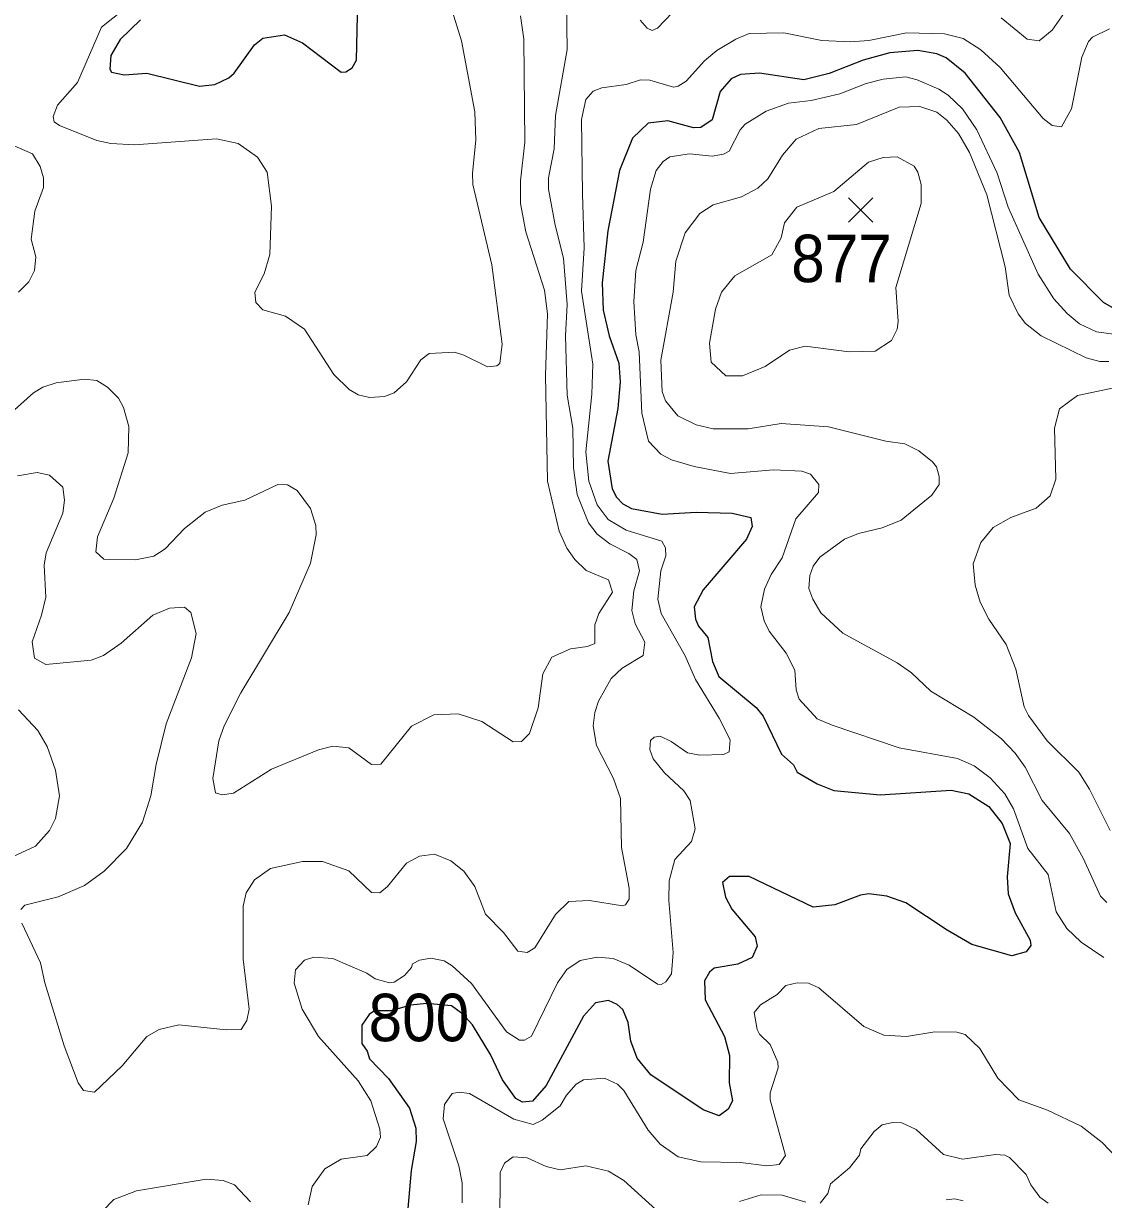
# Model space of a CAD drawing. Extents: x 265 to 291.4, y 7731.5 to 7759.6.
# Drawn here: x 281.619 to 283.439, y 7750.728 to 7752.709 of the extents above; entities that cross this region are included whole.
import ezdxf
from ezdxf.enums import TextEntityAlignment as Align

# ---------------------------------------------------------------- set-up
doc = ezdxf.new("R2010")
doc.units = 0
doc.header["$LTSCALE"] = 0.032
for name, color, linetype, lineweight in [('1', 7, 'Continuous', 25), ('2', 7, 'Continuous', 13), ('21', 7, 'Continuous', 25), ('61', 7, 'Continuous', 13)]:
    doc.layers.add(name, color=color, linetype=linetype, lineweight=lineweight)

msp = doc.modelspace()

# ---------------------------------------------------------------- linework, layer by layer
at = {"layer": '1'}
for points in [[(281.8164, 7752.7151), (281.7822, 7752.6817), (281.7663, 7752.6546), (281.7647, 7752.6316), (281.7671, 7752.6268), (281.7886, 7752.622), (281.8268, 7752.6252), (281.9159, 7752.6029), (281.9413, 7752.6061), (281.9652, 7752.6172), (281.9739, 7752.6252), (282.0081, 7752.6729), (282.0225, 7752.6841), (282.059, 7752.6896), (282.0893, 7752.6761), (282.1545, 7752.6268), (282.1625, 7752.6276), (282.1728, 7752.6339), (282.18, 7752.6467), (282.1823, 7752.7477)], [(283.4615, 7752.2258), (283.4392, 7752.2386), (283.3835, 7752.2951), (283.331, 7752.3818), (283.2976, 7752.4916), (283.265, 7752.5504), (283.2061, 7752.6252), (283.1743, 7752.6507), (283.1584, 7752.6578), (283.1266, 7752.6634), (283.0789, 7752.6594), (283.0343, 7752.6467), (282.9771, 7752.6244), (282.9341, 7752.614), (282.8593, 7752.6252), (282.8275, 7752.6228), (282.8116, 7752.6156), (282.7933, 7752.5942), (282.7797, 7752.5465), (282.7607, 7752.5337), (282.748, 7752.5329), (282.705, 7752.5448), (282.6716, 7752.5409), (282.6453, 7752.5154), (282.6238, 7752.4613), (282.6039, 7752.3595), (282.5944, 7752.272), (282.596, 7752.2259), (282.6063, 7752.1829), (282.6222, 7752.1368), (282.6246, 7752.105)], [(282.6246, 7752.105), (282.6206, 7752.0604), (282.6039, 7751.9713), (282.6111, 7751.9252), (282.6183, 7751.9109), (282.6294, 7751.8997), (282.6437, 7751.8917)], [(282.6437, 7751.8917), (282.6955, 7751.8822), (282.7527, 7751.8854), (282.8132, 7751.8838), (282.845, 7751.8766), (282.8474, 7751.8615), (282.8378, 7751.8401), (282.7646, 7751.755), (282.7495, 7751.7263), (282.7519, 7751.7056), (282.7567, 7751.6937), (282.7726, 7751.6746), (282.7805, 7751.634), (282.7909, 7751.6086), (282.8537, 7751.5568), (282.8657, 7751.5418), (282.8967, 7751.4781), (282.9166, 7751.4598), (282.923, 7751.4479), (282.9564, 7751.428), (282.985, 7751.4168), (283.063, 7751.4097), (283.1823, 7751.4176), (283.2125, 7751.4113), (283.2459, 7751.3898), (283.2682, 7751.3612), (283.2817, 7751.3278), (283.2769, 7751.2713), (283.2785, 7751.2427), (283.2904, 7751.2108), (283.3159, 7751.1647), (283.3167, 7751.1559), (283.3087, 7751.1448), (283.2849, 7751.1384), (283.2173, 7751.1575), (283.1759, 7751.1814), (283.1059, 7751.2275), (283.0741, 7751.2387), (283.0439, 7751.2426), (283.0296, 7751.2403), (282.9866, 7751.2243), (282.95, 7751.2204), (282.8418, 7751.2721), (282.8092, 7751.2721), (282.7973, 7751.2617), (282.802, 7751.2371), (282.8131, 7751.2172), (282.8521, 7751.1703), (282.8553, 7751.1544), (282.8474, 7751.1353), (282.8227, 7751.1241), (282.7829, 7751.1177), (282.775, 7751.1106), (282.767, 7751.0963), (282.7678, 7751.0645), (282.8004, 7751.0024), (282.8092, 7750.9706), (282.8084, 7750.9245), (282.814, 7750.8942), (282.8068, 7750.8799), (282.7917, 7750.8688), (282.7647, 7750.8791), (282.6764, 7750.9379), (282.6533, 7750.9658), (282.6429, 7750.9945), (282.6382, 7751.0263), (282.6294, 7751.0478), (282.6198, 7751.0565), (282.6048, 7751.0629), (282.5833, 7751.0589), (282.5626, 7751.0366), (282.4997, 7750.9197), (282.4767, 7750.8934), (282.46, 7750.8918), (282.4488, 7750.8982), (282.4266, 7750.9292), (282.4059, 7750.9722), (282.3757, 7751.0223), (282.3595, 7751.0402), (282.3402, 7751.0542), (282.299, 7751.0582), (282.2711, 7751.0555), (282.2386, 7751.0456), (282.2107, 7751.0456), (282.2014, 7751.0396), (282.1895, 7751.0215), (282.1895, 7750.9905), (282.1983, 7750.9777), (282.2022, 7750.965), (282.234, 7750.9316), (282.2698, 7750.8815), (282.2802, 7750.8481), (282.281, 7750.8258), (282.2722, 7750.7765), (282.2667, 7750.7129)]]:
    msp.add_lwpolyline(points, dxfattribs=at)
at = {"layer": '2'}
for points in [[(281.8268, 7752.7636), (281.7504, 7752.7024), (281.7098, 7752.6093), (281.6764, 7752.5711), (281.6693, 7752.552), (281.6708, 7752.5433), (281.6796, 7752.5369), (281.7425, 7752.5114), (281.7663, 7752.5067), (281.8061, 7752.5043), (281.9445, 7752.5146), (281.9811, 7752.5067), (282.0137, 7752.4836), (282.0296, 7752.4582), (282.0368, 7752.4009), (282.0344, 7752.3197), (282.0248, 7752.2871), (282.0089, 7752.2561), (282.0105, 7752.2386), (282.0225, 7752.2267), (282.0607, 7752.2155), (282.0925, 7752.194), (282.1418, 7752.1177), (282.168, 7752.0922), (282.1832, 7752.0835), (282.2023, 7752.0787), (282.2277, 7752.0803), (282.2436, 7752.0867), (282.2643, 7752.105), (282.2889, 7752.1423), (282.3025, 7752.1527), (282.3454, 7752.1551), (282.3613, 7752.1503), (282.4011, 7752.1304), (282.417, 7752.132), (282.4218, 7752.136), (282.4258, 7752.1686), (282.4083, 7752.3022), (282.3764, 7752.4375), (282.3756, 7752.4566), (282.3812, 7752.5123), (282.3796, 7752.56), (282.3574, 7752.6793), (282.3335, 7752.7557)], [(282.5729, 7751.2315), (282.6286, 7751.2228), (282.6334, 7751.2244), (282.6398, 7751.2339), (282.6398, 7751.2522), (282.627, 7751.3206), (282.6254, 7751.4033), (282.6135, 7751.4368), (282.5849, 7751.4924), (282.5793, 7751.5259), (282.5817, 7751.5481), (282.588, 7751.5672), (282.6095, 7751.6054), (282.6278, 7751.6229), (282.6636, 7751.6444), (282.666, 7751.6666), (282.6501, 7751.6977), (282.6445, 7751.72), (282.6477, 7751.7534), (282.6573, 7751.7868), (282.6525, 7751.8059), (282.639, 7751.8162), (282.6071, 7751.8321), (282.5857, 7751.8488), (282.5713, 7751.8679), (282.5523, 7751.9156), (282.5459, 7751.9602), (282.5451, 7752.027), (282.5355, 7752.0827), (282.5324, 7752.1829), (282.5355, 7752.2354), (282.5292, 7752.3134), (282.5149, 7752.3691), (282.5037, 7752.4295), (282.5037, 7752.4486), (282.5133, 7752.4979), (282.5157, 7752.5536), (282.5355, 7752.665), (282.534, 7752.7429)], [(283.2666, 7752.7183), (283.3104, 7752.6825), (283.331, 7752.6793), (283.3525, 7752.6976), (283.3923, 7752.7541)], [(282.4568, 7752.7215), (282.4624, 7752.6825), (282.464, 7752.5091), (282.4568, 7752.4438), (282.4568, 7752.4057), (282.4655, 7752.3579), (282.4974, 7752.2593)], [(282.6581, 7752.7143), (282.67, 7752.7008), (282.6787, 7752.6968), (282.6875, 7752.7008), (282.7129, 7752.727)], [(283.4496, 7752.7), (283.4209, 7752.6857), (283.4138, 7752.6785), (283.4026, 7752.6523), (283.3851, 7752.5648), (283.3684, 7752.5345), (283.3525, 7752.5369), (283.3374, 7752.5488), (283.265, 7752.6348), (283.2324, 7752.6642), (283.203, 7752.6833), (283.1712, 7752.6912), (283.1075, 7752.6928), (283.0439, 7752.6801), (283.0121, 7752.6777), (282.9643, 7752.6801), (282.9007, 7752.6928), (282.8418, 7752.692), (282.8195, 7752.6825), (282.7877, 7752.6634), (282.767, 7752.6459), (282.736, 7752.6117), (282.7225, 7752.6029), (282.7145, 7752.6013), (282.6748, 7752.6133), (282.6589, 7752.6141), (282.635, 7752.6061), (282.5936, 7752.6005), (282.5793, 7752.595), (282.5666, 7752.5807), (282.5594, 7752.5473), (282.561, 7752.4216), (282.5642, 7752.3309), (282.5594, 7752.2577), (282.5785, 7752.1352)], [(283.44, 7751.1353), (283.4018, 7751.1615), (283.3772, 7751.1846), (283.3597, 7751.2124), (283.3461, 7751.2753), (283.3119, 7751.319), (283.2873, 7751.3858), (283.273, 7751.4113), (283.2483, 7751.4384), (283.2213, 7751.4582), (283.1934, 7751.471), (283.0948, 7751.4885), (282.9818, 7751.5266), (282.9564, 7751.5378), (282.9261, 7751.5704), (282.9214, 7751.5863), (282.919, 7751.6197), (282.9047, 7751.6484), (282.876, 7751.685), (282.8673, 7751.7025), (282.8617, 7751.7263), (282.868, 7751.7557), (282.8792, 7751.7804), (282.8975, 7751.809), (282.9206, 7751.8743), (282.9587, 7751.9188), (282.9595, 7751.9323), (282.9452, 7751.9498), (282.9309, 7751.9546), (282.8832, 7751.957), (282.8108, 7751.9506), (282.7495, 7751.9626), (282.7114, 7751.9737), (282.6931, 7751.9832), (282.6724, 7752.0055), (282.6612, 7752.0525), (282.6565, 7752.1559), (282.6509, 7752.1845), (282.6477, 7752.2402), (282.6509, 7752.2927), (282.6636, 7752.3404), (282.6756, 7752.4295), (282.6851, 7752.4613), (282.697, 7752.4765), (282.7082, 7752.4844), (282.7416, 7752.4892), (282.7798, 7752.4852), (282.7989, 7752.4884), (282.8084, 7752.4939), (282.8267, 7752.5298), (282.8354, 7752.5393), (282.8705, 7752.5608), (282.9086, 7752.5743), (282.9468, 7752.5791), (282.9946, 7752.5902), (283.0391, 7752.6077), (283.0677, 7752.6149), (283.1059, 7752.6188), (283.125, 7752.6141), (283.1616, 7752.5982), (283.1775, 7752.5878), (283.2014, 7752.5648), (283.226, 7752.5298), (283.2602, 7752.4566), (283.2785, 7752.3993), (283.3294, 7752.2863), (283.3557, 7752.245), (283.378, 7752.2203), (283.3987, 7752.2028), (283.4273, 7752.1893), (283.4559, 7752.1853)], [(283.2427, 7752.42), (283.2133, 7752.4916), (283.195, 7752.5234), (283.1751, 7752.5457), (283.1584, 7752.5592), (283.1298, 7752.5687), (283.0948, 7752.5679), (283.0232, 7752.5385), (282.9596, 7752.5321), (282.9214, 7752.5138), (282.8983, 7752.4868), (282.8736, 7752.447), (282.8569, 7752.4311), (282.8291, 7752.4168), (282.7814, 7752.4033), (282.7591, 7752.3889), (282.7344, 7752.3563), (282.7185, 7752.3086), (282.7137, 7752.2561), (282.6931, 7752.1416), (282.6954, 7752.0891), (282.701, 7752.0731), (282.7217, 7752.0477), (282.7527, 7752.0326), (282.7814, 7752.0262), (282.8402, 7752.0262), (282.8959, 7752.0349), (282.9755, 7752.0294), (283.0725, 7752.0055), (283.1043, 7752.0007), (283.1282, 7751.9888), (283.1513, 7751.9705), (283.1576, 7751.9618), (283.1624, 7751.9459), (283.1624, 7751.9323), (283.1497, 7751.914), (283.098, 7751.8719), (283.0661, 7751.8591), (283.0264, 7751.8496), (283.0025, 7751.8401), (282.9611, 7751.8098), (282.95, 7751.7947), (282.9444, 7751.7788), (282.9428, 7751.7573), (282.9492, 7751.739), (282.9627, 7751.716), (283.0001, 7751.6818), (283.0916, 7751.6316), (283.1155, 7751.6149), (283.1481, 7751.5839), (283.2205, 7751.5402), (283.2674, 7751.5036), (283.2905, 7751.4797), (283.3072, 7751.4559), (283.3358, 7751.4002), (283.3819, 7751.3445), (283.405, 7751.3031), (283.4344, 7751.2387), (283.4448, 7751.2283)], [(281.6104, 7752.2561), (281.6279, 7752.2736), (281.6374, 7752.2927), (281.6398, 7752.3158), (281.6319, 7752.3452), (281.6382, 7752.3929), (281.6526, 7752.4327), (281.6526, 7752.4486), (281.647, 7752.4677), (281.6343, 7752.4892), (281.5865, 7752.5099)], [(283.4098, 7752.1455), (283.3342, 7752.1829), (283.308, 7752.2036), (283.2952, 7752.2195), (283.2801, 7752.2513), (283.2738, 7752.2991), (283.2427, 7752.42)], [(282.4974, 7752.2593), (282.5021, 7752.2195), (282.499, 7752.1161), (282.5021, 7751.9379), (282.522, 7751.8536), (282.5347, 7751.825), (282.5483, 7751.8059)], [(283.448, 7752.1392), (283.4329, 7752.1392), (283.4098, 7752.1455)], [(282.5785, 7752.1352), (282.5769, 7752.0843), (282.5666, 7751.9872), (282.5721, 7751.9379), (282.5857, 7751.8981), (282.6047, 7751.8735), (282.635, 7751.8552)], [(282.5483, 7751.8059), (282.5674, 7751.7876), (282.6048, 7751.7716), (282.6119, 7751.751), (282.5888, 7751.7152), (282.5817, 7751.6961), (282.5817, 7751.6643), (282.5698, 7751.6595), (282.5411, 7751.6555), (282.5093, 7751.6412), (282.4942, 7751.6134), (282.4862, 7751.5561), (282.4719, 7751.5131), (282.4584, 7751.4996), (282.4441, 7751.4988), (282.3916, 7751.533), (282.3518, 7751.5457), (282.3104, 7751.5441), (282.273, 7751.525), (282.2213, 7751.4614), (282.2054, 7751.4606), (282.1673, 7751.4885), (282.1402, 7751.4916), (282.1163, 7751.4853), (282.0368, 7751.4527), (281.9732, 7751.4121), (281.9541, 7751.4097), (281.9429, 7751.4129), (281.9381, 7751.4368), (281.9485, 7751.5004), (281.9572, 7751.5259), (281.9851, 7751.5815), (282.067, 7751.7168), (282.1028, 7751.7995), (282.1123, 7751.8472), (282.1116, 7751.8631), (282.1028, 7751.8918), (282.0805, 7751.922), (282.0638, 7751.9315), (282.0479, 7751.9323), (281.9922, 7751.9061), (281.9541, 7751.8973), (281.9254, 7751.8854), (281.8904, 7751.8584), (281.8578, 7751.8241), (281.8387, 7751.8114), (281.8077, 7751.8051), (281.7544, 7751.8066), (281.7409, 7751.8186), (281.744, 7751.844), (281.7711, 7751.9093), (281.7957, 7751.9856), (281.7965, 7752.0302), (281.7878, 7752.062), (281.779, 7752.0779), (281.7607, 7752.0962), (281.7425, 7752.1073), (281.7218, 7752.1097), (281.674, 7752.1034), (281.6518, 7752.0962), (281.6359, 7752.0867), (281.604, 7752.058)], [(283.4504, 7751.3493), (283.4154, 7751.4193), (283.3979, 7751.4479), (283.3445, 7751.5004), (283.3127, 7751.5434), (283.3056, 7751.5577), (283.2913, 7751.6213), (283.2753, 7751.6627), (283.2459, 7751.7056), (283.2316, 7751.7343), (283.2228, 7751.7629), (283.2197, 7751.7987), (283.2324, 7751.8345), (283.2531, 7751.86), (283.2833, 7751.8766), (283.3255, 7751.8926), (283.3493, 7751.9132), (283.3589, 7751.9411), (283.3565, 7752.027), (283.3652, 7752.0596), (283.3955, 7752.0819), (283.4623, 7752.0962)], [(281.6088, 7751.9467), (281.6422, 7751.9522), (281.6629, 7751.9482), (281.6852, 7751.9276), (281.6884, 7751.9061), (281.6852, 7751.8838), (281.6573, 7751.817), (281.6541, 7751.7963), (281.6565, 7751.7422), (281.6494, 7751.712), (281.6335, 7751.6674), (281.6374, 7751.6396), (281.6565, 7751.6292), (281.7329, 7751.6364), (281.7536, 7751.6444), (281.7838, 7751.665), (281.8371, 7751.712), (281.865, 7751.7239), (281.8904, 7751.7255), (281.9008, 7751.7168), (281.9103, 7751.681), (281.9023, 7751.6404), (281.8594, 7751.529), (281.8427, 7751.4606), (281.8339, 7751.4081), (281.8196, 7751.3636), (281.7926, 7751.319), (281.7552, 7751.2808), (281.7218, 7751.257), (281.6772, 7751.2379), (281.6215, 7751.2236), (281.6144, 7751.2164)], [(282.635, 7751.8552), (282.6946, 7751.8369), (282.701, 7751.8257), (282.7018, 7751.8122), (282.6931, 7751.7868), (282.6883, 7751.739), (282.6938, 7751.7152), (282.7344, 7751.6436), (282.7519, 7751.6038), (282.7917, 7751.5386), (282.81, 7751.502), (282.8084, 7751.4821), (282.7989, 7751.4773), (282.7591, 7751.4765), (282.7384, 7751.4805), (282.7106, 7751.4996), (282.6923, 7751.5083), (282.6819, 7751.5068), (282.6756, 7751.5012), (282.6748, 7751.4861), (282.6803, 7751.4702), (282.6994, 7751.4463), (282.732, 7751.4161), (282.7424, 7751.4002), (282.7511, 7751.3524), (282.7448, 7751.331), (282.7169, 7751.3007), (282.7074, 7751.2649), (282.7066, 7751.2315), (282.7137, 7751.144), (282.7113, 7751.1082), (282.7018, 7751.0947), (282.6939, 7751.0899), (282.6875, 7751.0907), (282.6398, 7751.1225), (282.6127, 7751.1337), (282.5857, 7751.1361), (282.557, 7751.1305), (282.5348, 7751.1154), (282.5188, 7751.0931), (282.4751, 7751.0032), (282.4632, 7750.9961), (282.4552, 7750.9961), (282.4329, 7751.0104), (282.3741, 7751.0915), (282.3414, 7751.1217), (282.3279, 7751.1297), (282.3057, 7751.1345), (282.2866, 7751.1313), (282.2746, 7751.1249), (282.273, 7751.1186), (282.2611, 7751.105), (282.2436, 7751.0939), (282.2357, 7751.0931), (282.2118, 7751.0995), (282.1975, 7751.109), (282.1402, 7751.1337), (282.1084, 7751.136), (282.0925, 7751.1313), (282.0773, 7751.1146), (282.075, 7751.0923), (282.0885, 7751.0486), (282.1163, 7751.0024), (282.1832, 7750.9276), (282.2046, 7750.8942), (282.2197, 7750.8465), (282.2205, 7750.833), (282.2142, 7750.8171), (282.1983, 7750.802), (282.1545, 7750.7956), (282.1267, 7750.7797), (282.1058, 7750.7499), (282.0988, 7750.7192)], [(281.5945, 7751.3023), (281.639, 7751.323), (281.6629, 7751.3492), (281.6732, 7751.3699), (281.6796, 7751.4081), (281.6732, 7751.4511), (281.6589, 7751.4909), (281.643, 7751.5179), (281.6104, 7751.5529)], [(281.616, 7751.1933), (281.6478, 7751.1265), (281.6549, 7751.0931), (281.6876, 7750.9865), (281.7114, 7750.9245), (281.7202, 7750.9117), (281.7385, 7750.9085), (281.7854, 7750.9531), (281.8268, 7751.0024), (281.8475, 7751.0143), (281.8809, 7751.0223), (281.9604, 7751.0135), (281.9859, 7751.0143), (281.9954, 7751.0295), (281.9994, 7751.0486), (281.9891, 7751.1329), (281.9891, 7751.222), (281.9946, 7751.2443), (282.0081, 7751.2665), (282.0352, 7751.2856), (282.0893, 7751.2975), (282.1227, 7751.2975), (282.1673, 7751.2816), (282.2054, 7751.245), (282.2197, 7751.2442), (282.2325, 7751.2554), (282.2643, 7751.2944), (282.2866, 7751.3063), (282.312, 7751.3095), (282.3391, 7751.2983), (282.3613, 7751.2808), (282.3796, 7751.2554), (282.3979, 7751.2085), (282.4282, 7751.1774)], [(282.4282, 7751.1774), (282.452, 7751.1464), (282.4679, 7751.144), (282.4807, 7751.152), (282.5157, 7751.2077), (282.5379, 7751.2299), (282.5729, 7751.2315)], [(282.3582, 7750.7224), (282.3582, 7750.7558), (282.3526, 7750.7845), (282.3263, 7750.864), (282.3287, 7750.8879), (282.3414, 7750.9062), (282.3534, 7750.9085), (282.3709, 7750.9062), (282.4457, 7750.8632), (282.4783, 7750.8544), (282.4934, 7750.8616), (282.5236, 7750.8855), (282.534, 7750.9038), (282.5507, 7750.9221), (282.5626, 7750.9292), (282.5984, 7750.9324), (282.6199, 7750.9221), (282.631, 7750.9117), (282.6716, 7750.8449), (282.6923, 7750.821), (282.7225, 7750.7996), (282.7607, 7750.7916), (282.8275, 7750.79), (282.872, 7750.7844), (282.8927, 7750.7868), (282.9031, 7750.802), (282.8776, 7750.8958), (282.8776, 7750.9077), (282.8911, 7750.9499), (282.8903, 7750.9595), (282.8776, 7750.9889), (282.8593, 7751.0064), (282.8553, 7751.0143), (282.8506, 7751.043), (282.8609, 7751.0557), (282.8895, 7751.0732), (282.9039, 7751.0883), (282.923, 7751.0931), (282.9421, 7751.0923), (282.9596, 7751.0843), (283.0351, 7751.0191), (283.0693, 7751.0048), (283.1075, 7751.0024), (283.1552, 7751.0104), (283.1918, 7751.0096)], [(283.1918, 7751.0096), (283.2061, 7751.0056), (283.2308, 7750.9825), (283.261, 7750.9324), (283.2968, 7750.8958), (283.3446, 7750.8783), (283.4018, 7750.8513)], [(283.1696, 7750.8035), (283.1234, 7750.8457), (283.0996, 7750.8568), (283.0836, 7750.8576), (283.0661, 7750.8537), (283.0526, 7750.8425), (283.0303, 7750.8131), (283.028, 7750.8028), (283.0112, 7750.7813), (282.9794, 7750.7542), (282.9747, 7750.7383), (282.9619, 7750.7216)], [(283.4018, 7750.8513), (283.4368, 7750.8242), (283.4615, 7750.798)], [(282.6907, 7750.7057), (282.631, 7750.7598), (282.6048, 7750.7757), (282.5666, 7750.7844), (282.5236, 7750.7781), (282.4998, 7750.7837), (282.4679, 7750.798), (282.4441, 7750.7996), (282.4298, 7750.7892), (282.4226, 7750.7733), (282.4218, 7750.6874)], [(283.3167, 7750.7526), (283.3088, 7750.7701), (283.2809, 7750.7988), (283.273, 7750.8027), (283.2571, 7750.8035), (283.2014, 7750.7956), (283.1696, 7750.8035)], [(282.0018, 7750.724), (281.9747, 7750.7526), (281.9557, 7750.7598), (281.927, 7750.7622), (281.8093, 7750.7423), (281.7711, 7750.728), (281.7337, 7750.689)], [(282.9373, 7750.7232), (282.8975, 7750.7351), (282.8625, 7750.7359), (282.8259, 7750.7248)], [(283.3462, 7750.7216), (283.3318, 7750.732), (283.3167, 7750.7526)], [(283.1743, 7750.7272), (283.1887, 7750.7288), (283.203, 7750.7256)]]:
    msp.add_lwpolyline(points, dxfattribs=at)
msp.add_lwpolyline([(282.8962, 7752.3479), (282.9015, 7752.373), (282.9222, 7752.3993), (282.985, 7752.4255), (283.0431, 7752.4749), (283.0677, 7752.4828), (283.0916, 7752.4844), (283.1202, 7752.4685), (283.1266, 7752.4582), (283.1322, 7752.4375), (283.1322, 7752.4057), (283.0892, 7752.2641), (283.0932, 7752.2068), (283.0916, 7752.1941), (283.082, 7752.175), (283.0542, 7752.1567), (283.0105, 7752.1559), (282.9365, 7752.1654), (282.9102, 7752.1583), (282.8689, 7752.1312), (282.8307, 7752.1153), (282.8028, 7752.1153), (282.7782, 7752.1384), (282.775, 7752.1702), (282.7853, 7752.2275), (282.7957, 7752.2561), (282.8179, 7752.2839), (282.88, 7752.3189)], close=True, dxfattribs=at)
at = {"layer": '21'}
for p, q in [((283.0093, 7752.4153), (283.0505, 7752.3741)), ((283.0505, 7752.4153), (283.0093, 7752.3741))]:
    msp.add_line(p, q, dxfattribs=at)

# ---------------------------------------------------------------- texts
at = {"layer": '61', "width": 0.95}
for s, p in [('877', (282.9977, 7752.273)), ('800', (282.2855, 7750.9945))]:
    msp.add_text(s, height=0.08, dxfattribs=at).set_placement(p, align=Align.CENTER)

doc.saveas('drawing.dxf')
